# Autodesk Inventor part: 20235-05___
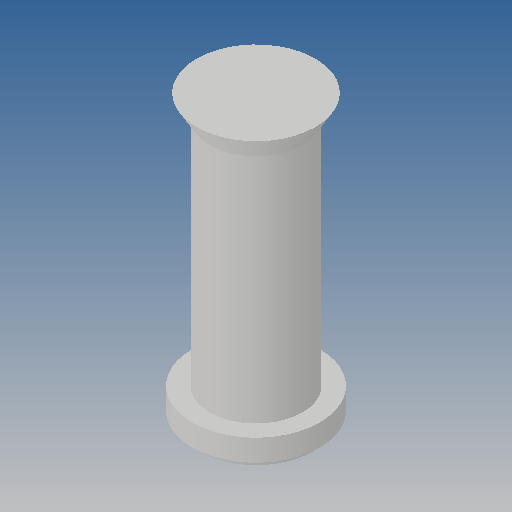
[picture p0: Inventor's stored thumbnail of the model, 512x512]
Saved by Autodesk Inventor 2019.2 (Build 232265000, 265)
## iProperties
Created: 2010-06
Part Number: 20235-05___
Material: Ogólny
Document SubType Name: Modeling
Designer: CADENGINEERING4
Density: 1 g/cm^3
Appearance: Domyślna
Author: CADENGINEERING4
Revision Number: ANY
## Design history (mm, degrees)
feature "NONE"
node "Bryła1"
